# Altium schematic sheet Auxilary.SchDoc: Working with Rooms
size 431 x 279 mm; Organization: Altium Limited; Address1: L3, 12a Rodborough Rd; Address2: Frenchs Forest; Address3: NSW; Address4: Australia 2086; DocumentNumber: 1; SheetNumber: 1; SheetTotal: 8
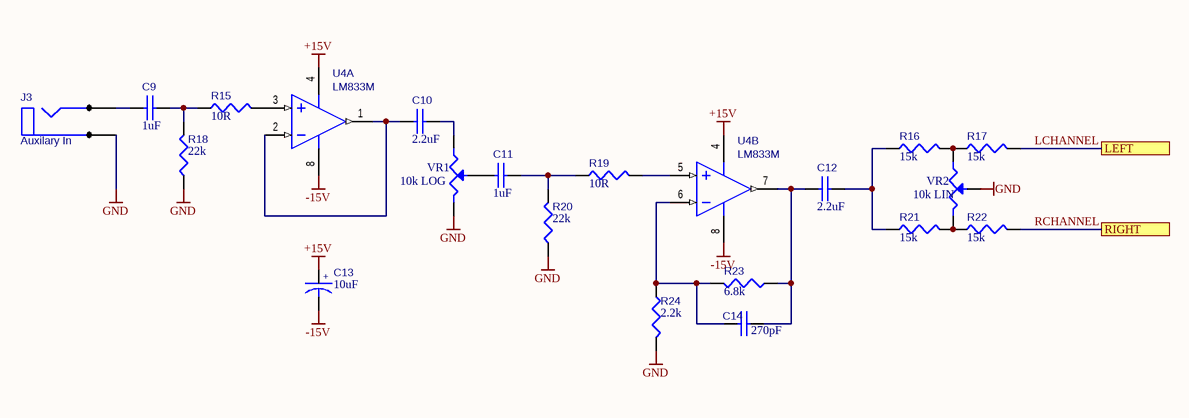
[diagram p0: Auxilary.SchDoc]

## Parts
C9  1uF  [RB.2/.4-NP]
C10  2.2uF  [RB.2/.4-NP]
C11  1uF  [RB.2/.4-NP]
C12  2.2uF  [RB.2/.4-NP]
C13  10uF  [RB.2/.4]
C14  270pF  [RAD0.2]
J3  Auxilary In  [JACK-6.25MM]
R15  10R  [AXIAL0.4]
R16  15k  [AXIAL0.4]
R17  15k  [AXIAL0.4]
R18  22k  [AXIAL0.4]
R19  10R  [AXIAL0.4]
R20  22k  [AXIAL0.4]
R21  15k  [AXIAL0.4]
R22  15k  [AXIAL0.4]
R23  6.8k  [AXIAL0.4]
R24  2.2k  [AXIAL0.4]
U4  LM833M  [DIP8]  (parts A,B of 2)
VR1  10k LOG  [POT - 24MM]
VR2  10k LIN  [POT - 24MM]

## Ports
LEFT, RIGHT

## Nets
+15V: C13.1 U4.4(V-)
-15V: C13.2 U4.8(V+)
GND: J3.3(C) R18.1 R20.1 R24.2 VR1.3 VR2.2(W)
LCHANNEL: R17.2 ; port LEFT
RCHANNEL: R22.2 ; port RIGHT
NetC9_1: C9.1 J3.1(A)
NetC9_2: C9.2 R15.1 R18.2
NetC10_1: C10.1 U4.1(OUT1) U4.2(IN1-)
NetC10_2: C10.2 VR1.1
NetC11_1: C11.1 VR1.2(W)
NetC11_2: C11.2 R19.1 R20.2
NetC12_1: C12.1 C14.2 R23.1 U4.7(OUT2)
NetC12_2: C12.2 R16.1 R21.1
NetC14_1: C14.1 R23.2 R24.1 U4.6(IN2-)
NetR15_2: R15.2 U4.3(IN1+)
NetR16_2: R16.2 R17.1 VR2.1
NetR19_2: R19.2 U4.5(IN2+)
NetR21_2: R21.2 R22.1 VR2.3

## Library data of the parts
C9-C12 C14 = CAP: Capacitor
C13 = CAPACITOR POL: Bi-Polar Capacitor
J3 = PHONEJACK MONO
R15-R24 = RES1: Resistor
U4 = LM833M: Fast Settling Dual Operational Amplifier
VR1 VR2 = POT1: Potentiometer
